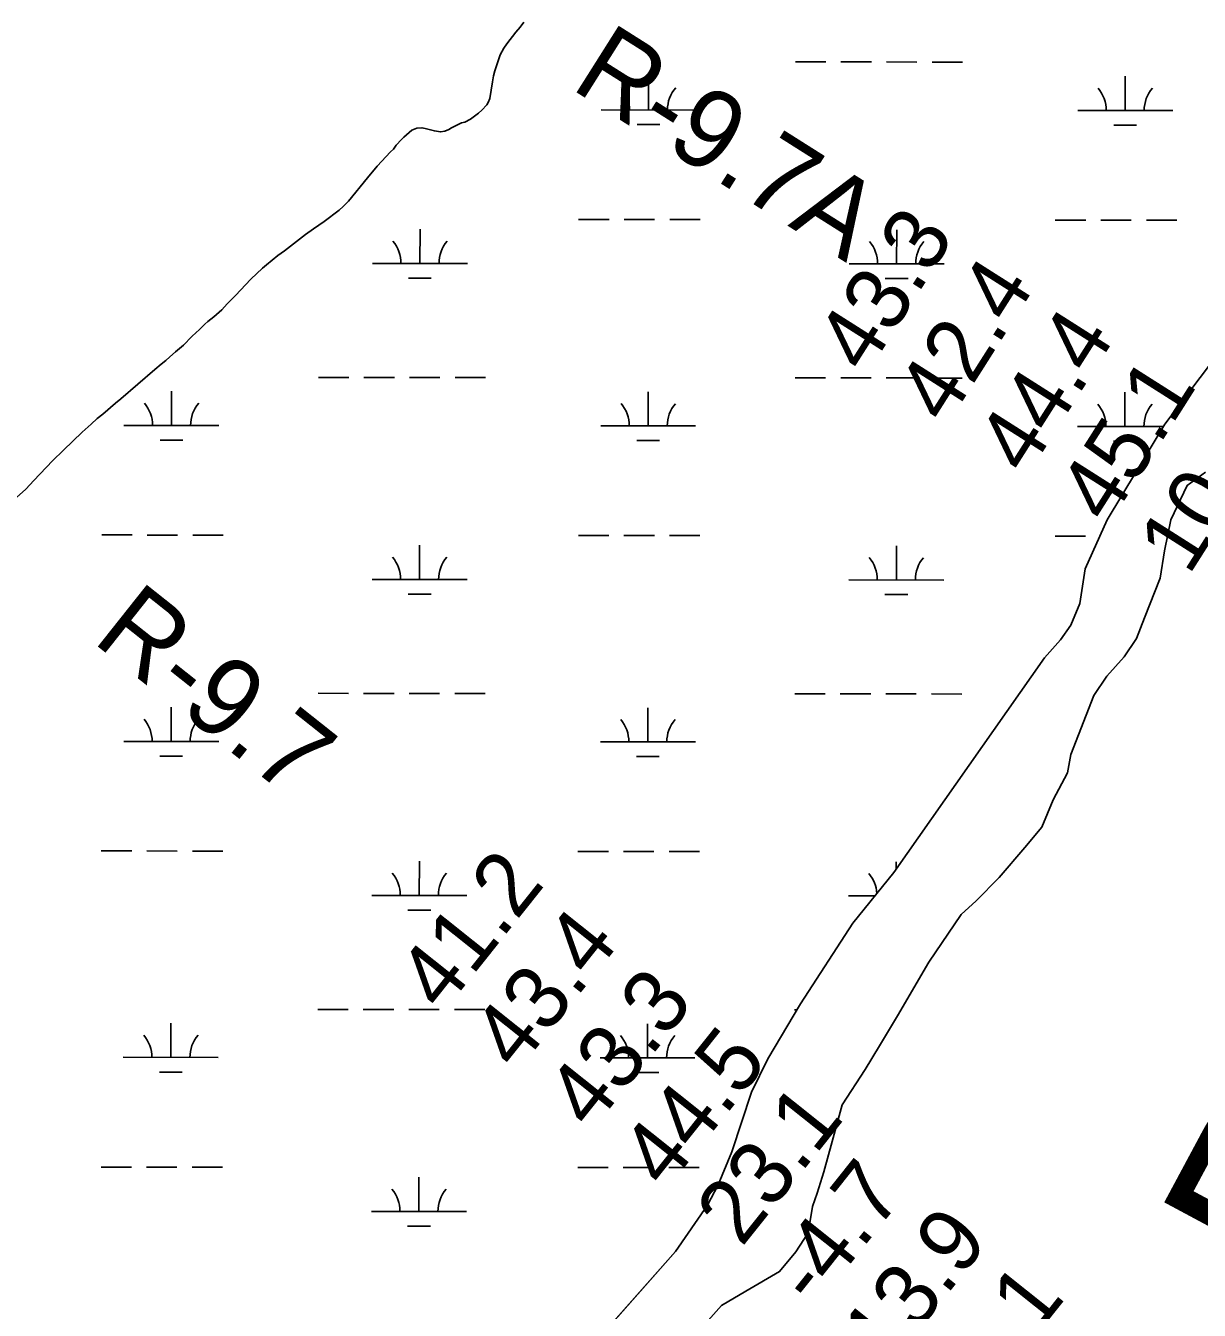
# Model space of a CAD drawing. Extents: x 3148686 to 3186545, y 916144 to 941516.
# Drawn here: x 3156578 to 3157813, y 924661 to 926013 of the extents above; entities that cross this region are included whole.
import ezdxf

# ---------------------------------------------------------------- set-up
doc = ezdxf.new("R2010")
doc.units = 0
for name, color, linetype in [('V-RIVR-EDGE', 7, 'Continuous'), ('V-RIVR-IDEN', 7, 'Continuous'), ('V-RIVR-RANG', 7, 'Continuous'), ('V-RIVR-RANG-IDEN', 7, 'Continuous'), ('V-SITE-VEGE', 7, 'Continuous'), ('V-TOPO-SHOR', 7, 'Continuous'), ('V-WETL-SWMP', 7, 'Continuous')]:
    doc.layers.add(name, color=color, linetype=linetype)

msp = doc.modelspace()

# ---------------------------------------------------------------- linework, layer by layer
at = {"layer": 'V-RIVR-EDGE'}
msp.add_lwpolyline([(3157819.9, 925543.4), (3157800.7, 925529.3), (3157783.3, 925493.1), (3157776.8, 925460.5), (3157772.1, 925431.8), (3157755.7, 925390), (3157747.1, 925368), (3157734.3, 925348.9), (3157716.2, 925328.4), (3157702.3, 925308.2), (3157678, 925245.9), (3157674.5, 925226.7), (3157659.5, 925198.4), (3157647.7, 925169.4), (3157629.6, 925148.1), (3157602.6, 925116.6), (3157578.4, 925091.9), (3157562.7, 925077.7), (3157528.6, 925027.5), (3157512.9, 925000.2), (3157496.5, 924972.6), (3157476.6, 924939.3), (3157461.6, 924914.5), (3157437.4, 924877.3), (3157426.7, 924838.7), (3157418.1, 924806.5), (3157411, 924784.1), (3157406.3, 924770), (3157401.6, 924742.3), (3157388.5, 924722.5), (3157371.4, 924701.6), (3157335.9, 924681.1), (3157310.3, 924666), (3157293.6, 924646.9)], dxfattribs=at)
at = {"layer": 'V-SITE-VEGE'}
for p, q in [((3157098.3, 926011.8), (3157093.7, 926006.6)), ((3157102.3, 926016.9), (3157098.3, 926011.8)), ((3157093.7, 926006.6), (3157084.2, 925994.2)), ((3157077.4, 925982.6), (3157071.8, 925965.8)), ((3157081, 925989.5), (3157077.4, 925982.6)), ((3157084.2, 925994.2), (3157081, 925989.5)), ((3157070.4, 925960.4), (3157069.2, 925954.3)), ((3157071.8, 925965.8), (3157070.4, 925960.4)), ((3157069.2, 925954.3), (3157066.3, 925936.5)), ((3157063.1, 925929.8), (3157058, 925924.4)), ((3157064.7, 925932.3), (3157063.1, 925929.8)), ((3157066.3, 925936.5), (3157064.7, 925932.3)), ((3157046.1, 925914.8), (3157040.1, 925911.6)), ((3157050.4, 925917.9), (3157046.1, 925914.8)), ((3157054.4, 925921.1), (3157050.4, 925917.9)), ((3157058, 925924.4), (3157054.4, 925921.1)), ((3156984.1, 925903.4), (3156975.7, 925895.9)), ((3156989.6, 925905.5), (3156984.1, 925903.4)), ((3156994.8, 925905.9), (3156989.6, 925905.5)), ((3156998.3, 925905.1), (3156994.8, 925905.9)), ((3157008, 925902.5), (3156998.3, 925905.1)), ((3157014.5, 925901.5), (3157008, 925902.5)), ((3157019.1, 925902.4), (3157014.5, 925901.5)), ((3157023.3, 925904), (3157019.1, 925902.4)), ((3157026, 925905.6), (3157023.3, 925904)), ((3157036.4, 925910.9), (3157026, 925905.6)), ((3157040.1, 925911.6), (3157036.4, 925910.9)), ((3156967.8, 925887.4), (3156964.8, 925883.4)), ((3156973.4, 925893.5), (3156967.8, 925887.4)), ((3156975.7, 925895.9), (3156973.4, 925893.5)), ((3156961.8, 925880.5), (3156947.9, 925865.3)), ((3156964.8, 925883.4), (3156961.8, 925880.5)), ((3156947.9, 925865.3), (3156937.6, 925853.1)), ((3156937.6, 925853.1), (3156917.5, 925828.6)), ((3156912.1, 925822.9), (3156907.6, 925818.9)), ((3156917.5, 925828.6), (3156912.1, 925822.9)), ((3156891.9, 925807.1), (3156880.8, 925799.3)), ((3156907.6, 925818.9), (3156891.9, 925807.1)), ((3156872.2, 925793.5), (3156850.2, 925776.4)), ((3156880.8, 925799.3), (3156872.2, 925793.5)), ((3156843.3, 925771.3), (3156831.3, 925761.6)), ((3156850.2, 925776.4), (3156843.3, 925771.3)), ((3156827.2, 925757.9), (3156814.9, 925746.3)), ((3156831.3, 925761.6), (3156827.2, 925757.9)), ((3156814.9, 925746.3), (3156798.6, 925729.1)), ((3156798.6, 925729.1), (3156789.8, 925720.4)), ((3156784.1, 925714.3), (3156775.9, 925706.8)), ((3156789.8, 925720.4), (3156784.1, 925714.3)), ((3156766.4, 925699), (3156760.4, 925693)), ((3156769.6, 925701.7), (3156766.4, 925699)), ((3156775.9, 925706.8), (3156769.6, 925701.7)), ((3156752.7, 925685.9), (3156743.7, 925677.1)), ((3156757.2, 925690.3), (3156752.7, 925685.9)), ((3156760.4, 925693), (3156757.2, 925690.3)), ((3156743.7, 925677.1), (3156735.6, 925669.8)), ((3157777, 925593.7), (3157841.7, 925679.2)), ((3156725.1, 925660.9), (3156720.5, 925656.8)), ((3156729.4, 925664.5), (3156725.1, 925660.9)), ((3156735.6, 925669.8), (3156729.4, 925664.5)), ((3156713.8, 925651.3), (3156677.8, 925620.5)), ((3156720.5, 925656.8), (3156713.8, 925651.3)), ((3156677.8, 925620.5), (3156672.1, 925616)), ((3156658.8, 925604.4), (3156653, 925599.6)), ((3156672.1, 925616), (3156658.8, 925604.4)), ((3156646.8, 925593.9), (3156637.3, 925585.5)), ((3156653, 925599.6), (3156646.8, 925593.9)), ((3157716.5, 925493.1), (3157777, 925593.7)), ((3156637.3, 925585.5), (3156617.4, 925566.5)), ((3156617.4, 925566.5), (3156606.1, 925555.3)), ((3156606.1, 925555.3), (3156586.4, 925534.4)), ((3156586.4, 925534.4), (3156577.7, 925525.3)), ((3157693.2, 925441.4), (3157716.5, 925493.1)), ((3157687.6, 925404.8), (3157693.2, 925441.4)), ((3157678.2, 925382.2), (3157687.6, 925404.8)), ((3157667.1, 925366.7), (3157678.2, 925382.2)), ((3157650.4, 925347.7), (3157667.1, 925366.7)), ((3157491.7, 925121.7), (3157650.4, 925347.7)), ((3157448.5, 925068.4), (3157491.7, 925121.7)), ((3157393.5, 924983.6), (3157448.5, 925068.4)), ((3157359.1, 924925.6), (3157393.5, 924983.6)), ((3157342, 924890.6), (3157359.1, 924925.6)), ((3157321.1, 924827.6), (3157342, 924890.6)), ((3157306.9, 924792.8), (3157321.1, 924827.6)), ((3157295.5, 924771.6), (3157306.9, 924792.8)), ((3157261.8, 924722.8), (3157295.5, 924771.6)), ((3157145.2, 924591), (3157261.8, 924722.8))]:
    msp.add_line(p, q, dxfattribs=at)
at = {"layer": 'V-TOPO-SHOR'}
for points in [[(3157014.5, 925901.5), (3157019.1, 925902.4), (3157023.3, 925904), (3157026, 925905.6), (3157036.4, 925910.9), (3157040.1, 925911.6), (3157046.1, 925914.8), (3157050.4, 925917.9), (3157054.4, 925921.1), (3157058, 925924.4), (3157063.1, 925929.8), (3157064.7, 925932.3), (3157066.3, 925936.5), (3157069.2, 925954.3), (3157070.4, 925960.4), (3157071.8, 925965.8), (3157077.4, 925982.6), (3157081, 925989.5), (3157084.2, 925994.2), (3157093.7, 926006.6), (3157098.3, 926011.8), (3157102.3, 926016.9)], [(3156565, 925513.9), (3156577.7, 925525.3), (3156586.4, 925534.4), (3156606.1, 925555.3), (3156617.4, 925566.5), (3156637.3, 925585.5), (3156646.8, 925593.9), (3156653, 925599.6), (3156658.8, 925604.4), (3156672.1, 925616), (3156677.8, 925620.5), (3156713.8, 925651.3), (3156720.5, 925656.8), (3156725.1, 925660.9), (3156729.4, 925664.5), (3156735.6, 925669.8), (3156743.7, 925677.1), (3156752.7, 925685.9), (3156757.2, 925690.3), (3156760.4, 925693), (3156766.4, 925699), (3156769.6, 925701.7), (3156775.9, 925706.8), (3156784.1, 925714.3), (3156789.8, 925720.4), (3156798.6, 925729.1), (3156814.9, 925746.3), (3156827.2, 925757.9), (3156831.3, 925761.6), (3156843.3, 925771.3), (3156850.2, 925776.4), (3156872.2, 925793.5), (3156880.8, 925799.3), (3156891.9, 925807.1), (3156907.6, 925818.9), (3156912.1, 925822.9), (3156917.5, 925828.6), (3156937.6, 925853.1), (3156947.9, 925865.3), (3156961.8, 925880.5), (3156964.8, 925883.4), (3156967.8, 925887.4), (3156973.4, 925893.5), (3156975.7, 925895.9), (3156984.1, 925903.4), (3156989.6, 925905.5), (3156994.8, 925905.9), (3156998.3, 925905.1), (3157008, 925902.5), (3157014.5, 925901.5)]]:
    msp.add_lwpolyline(points, dxfattribs=at)
at = {"layer": 'V-WETL-SWMP'}
for p, q in [((3157388.1, 925975.2), (3157420.1, 925975.1)), ((3157436.1, 925975.1), (3157468.1, 925975.1)), ((3157484.1, 925975.1), (3157516.1, 925975)), ((3157532.1, 925975), (3157564.1, 925975)), ((3157233.5, 925924.6), (3157233.5, 925960.6)), ((3157735.4, 925924.1), (3157735.4, 925960.1)), ((3157183.5, 925924.6), (3157283.5, 925924.5)), ((3157685.4, 925924.1), (3157785.4, 925924)), ((3157221.5, 925909.2), (3157245.5, 925909.2)), ((3157723.4, 925908.6), (3157747.4, 925908.6)), ((3157159.9, 925809.2), (3157191.9, 925809.2)), ((3157207.9, 925809.2), (3157239.9, 925809.2)), ((3157255.9, 925809.1), (3157287.9, 925809.1)), ((3157661.8, 925808.7), (3157693.8, 925808.7)), ((3157709.8, 925808.7), (3157741.8, 925808.6)), ((3157757.8, 925808.6), (3157789.8, 925808.6)), ((3156992.8, 925763), (3156992.9, 925799)), ((3157494.7, 925762.5), (3157494.8, 925798.5)), ((3156942.8, 925763), (3157042.8, 925762.9)), ((3157444.7, 925762.5), (3157544.7, 925762.4)), ((3156980.8, 925747.6), (3157004.8, 925747.5)), ((3157482.7, 925747), (3157506.7, 925747)), ((3156885.9, 925643), (3156917.9, 925643)), ((3156933.9, 925643), (3156965.9, 925642.9)), ((3156981.9, 925642.9), (3157013.9, 925642.9)), ((3157029.9, 925642.9), (3157061.9, 925642.8)), ((3157387.8, 925642.5), (3157419.8, 925642.5)), ((3157435.8, 925642.4), (3157467.8, 925642.4)), ((3157483.8, 925642.4), (3157515.8, 925642.4)), ((3157531.8, 925642.3), (3157563.8, 925642.3)), ((3156731.2, 925592.4), (3156731.2, 925628.4)), ((3157233.1, 925591.9), (3157233.2, 925627.9)), ((3157735, 925591.4), (3157735.1, 925627.4)), ((3156681.2, 925592.5), (3156781.2, 925592.4)), ((3157183.1, 925592), (3157283.1, 925591.9)), ((3157685, 925591.4), (3157775.6, 925591.3)), ((3156719.2, 925577), (3156743.2, 925577)), ((3157221.1, 925576.5), (3157245.1, 925576.5)), ((3157723, 925576), (3157747, 925575.9)), ((3156657.7, 925477.1), (3156689.7, 925477.1)), ((3156705.7, 925477), (3156737.7, 925477)), ((3156753.7, 925477), (3156785.7, 925477)), ((3157159.6, 925476.6), (3157191.6, 925476.5)), ((3157207.6, 925476.5), (3157239.6, 925476.5)), ((3157255.6, 925476.5), (3157287.6, 925476.4)), ((3157661.5, 925476), (3157693.5, 925476)), ((3156992.5, 925430.3), (3156992.5, 925466.3)), ((3157494.4, 925429.8), (3157494.4, 925465.8)), ((3156942.5, 925430.4), (3157042.5, 925430.3)), ((3157444.4, 925429.8), (3157544.4, 925429.7)), ((3156980.5, 925414.9), (3157004.5, 925414.9)), ((3157482.4, 925414.4), (3157506.4, 925414.3)), ((3156885.5, 925310.4), (3156917.5, 925310.3)), ((3156933.5, 925310.3), (3156965.5, 925310.3)), ((3156981.5, 925310.3), (3157013.5, 925310.2)), ((3157029.5, 925310.2), (3157061.5, 925310.2)), ((3157387.4, 925309.8), (3157419.4, 925309.8)), ((3157435.4, 925309.8), (3157467.4, 925309.7)), ((3157483.4, 925309.7), (3157515.4, 925309.7)), ((3157531.4, 925309.7), (3157563.4, 925309.6)), ((3156730.9, 925259.8), (3156730.9, 925295.8)), ((3157232.8, 925259.2), (3157232.8, 925295.2)), ((3156680.9, 925259.8), (3156780.9, 925259.7)), ((3157182.8, 925259.3), (3157282.8, 925259.2)), ((3156718.8, 925244.4), (3156742.8, 925244.3)), ((3157220.8, 925243.8), (3157244.8, 925243.8)), ((3156657.3, 925144.4), (3156689.3, 925144.4)), ((3156705.3, 925144.4), (3156737.3, 925144.3)), ((3156753.3, 925144.3), (3156785.3, 925144.3)), ((3157159.2, 925143.9), (3157191.2, 925143.9)), ((3157207.2, 925143.8), (3157239.2, 925143.8)), ((3157255.2, 925143.8), (3157287.2, 925143.8)), ((3156992.1, 925097.6), (3156992.2, 925133.6)), ((3157494.1, 925125.1), (3157494.1, 925133.1)), ((3156942.1, 925097.7), (3157042.1, 925097.6)), ((3157444, 925097.2), (3157471.8, 925097.1)), ((3156980.1, 925082.2), (3157004.1, 925082.2)), ((3156885.2, 924977.7), (3156917.2, 924977.6)), ((3156933.2, 924977.6), (3156965.2, 924977.6)), ((3156981.2, 924977.6), (3157013.2, 924977.5)), ((3157029.2, 924977.5), (3157061.2, 924977.5)), ((3157387.1, 924977.1), (3157389.7, 924977.1)), ((3156730.5, 924927.1), (3156730.5, 924963.1)), ((3157232.4, 924926.6), (3157232.5, 924962.6)), ((3156680.5, 924927.2), (3156780.5, 924927)), ((3157182.4, 924926.6), (3157282.4, 924926.5)), ((3156718.5, 924911.7), (3156742.5, 924911.7)), ((3157220.4, 924911.2), (3157244.4, 924911.1)), ((3156657, 924811.7), (3156689, 924811.7)), ((3156705, 924811.7), (3156737, 924811.7)), ((3156753, 924811.6), (3156785, 924811.6)), ((3157158.9, 924811.2), (3157190.9, 924811.2)), ((3157206.9, 924811.2), (3157238.9, 924811.1)), ((3157254.9, 924811.1), (3157286.9, 924811.1)), ((3156991.8, 924765), (3156991.8, 924801)), ((3156941.8, 924765), (3157041.8, 924764.9)), ((3156979.8, 924749.5), (3157003.8, 924749.5))]:
    msp.add_line(p, q, dxfattribs=at)
for points in [[(3157102.3, 926016.9), (3157098.3, 926011.8), (3157093.7, 926006.6), (3157084.2, 925994.2), (3157081, 925989.5), (3157077.4, 925982.6), (3157071.8, 925965.8), (3157070.4, 925960.4), (3157069.2, 925954.3), (3157066.3, 925936.5), (3157064.7, 925932.3), (3157063.1, 925929.8), (3157058, 925924.4), (3157054.4, 925921.1), (3157050.4, 925917.9), (3157046.1, 925914.8), (3157040.1, 925911.6), (3157036.4, 925910.9), (3157026, 925905.6), (3157023.3, 925904), (3157019.1, 925902.4), (3157014.5, 925901.5), (3157008, 925902.5), (3156998.3, 925905.1), (3156994.8, 925905.9), (3156989.6, 925905.5), (3156984.1, 925903.4), (3156975.7, 925895.9), (3156973.4, 925893.5), (3156967.8, 925887.4), (3156964.8, 925883.4), (3156961.8, 925880.5), (3156947.9, 925865.3), (3156937.6, 925853.1), (3156917.5, 925828.6), (3156912.1, 925822.9), (3156907.6, 925818.9), (3156891.9, 925807.1), (3156880.8, 925799.3), (3156872.2, 925793.5), (3156850.2, 925776.4), (3156843.3, 925771.3), (3156831.3, 925761.6), (3156827.2, 925757.9), (3156814.9, 925746.3), (3156798.6, 925729.1), (3156789.8, 925720.4), (3156784.1, 925714.3), (3156775.9, 925706.8), (3156769.6, 925701.7), (3156766.4, 925699), (3156760.4, 925693), (3156757.2, 925690.3), (3156752.7, 925685.9), (3156743.7, 925677.1), (3156735.6, 925669.8), (3156729.4, 925664.5), (3156725.1, 925660.9), (3156720.5, 925656.8), (3156713.8, 925651.3), (3156677.8, 925620.5), (3156672.1, 925616), (3156658.8, 925604.4), (3156653, 925599.6), (3156646.8, 925593.9), (3156637.3, 925585.5), (3156617.4, 925566.5), (3156606.1, 925555.3), (3156586.4, 925534.4), (3156577.7, 925525.3), (3156565, 925513.9)], [(3157145.2, 924591), (3157261.8, 924722.8), (3157295.5, 924771.6), (3157306.9, 924792.8), (3157321.1, 924827.6), (3157342, 924890.6), (3157359.1, 924925.6), (3157393.5, 924983.6), (3157448.5, 925068.4), (3157491.7, 925121.7), (3157650.4, 925347.7), (3157667.1, 925366.7), (3157678.2, 925382.2), (3157687.6, 925404.8), (3157693.2, 925441.4), (3157716.5, 925493.1), (3157777, 925593.7), (3157841.7, 925679.2)]]:
    msp.add_lwpolyline(points, dxfattribs=at)
for centre, start, end in [((3157178.2, 925925.1), 359.1678, 40.7115), ((3157288.7, 925925), 139.1678, 180.7115), ((3157680.1, 925924.6), 359.1678, 40.7115), ((3157790.6, 925924.5), 139.1678, 180.7115), ((3156937.6, 925763.5), 359.1678, 40.7115), ((3157048.1, 925763.4), 139.1678, 180.7115), ((3157439.5, 925763), 359.1678, 40.7115), ((3157550, 925762.9), 139.1678, 180.7115), ((3156676, 925593), 359.1678, 40.7115), ((3156786.5, 925592.9), 139.1678, 180.7115), ((3157177.9, 925592.5), 359.1678, 40.7115), ((3157288.4, 925592.3), 139.1678, 180.7115), ((3157679.8, 925591.9), 359.1678, 40.7115), ((3157790.3, 925591.8), 139.1678, 180.7115), ((3156937.2, 925430.8), 359.1678, 40.7115), ((3157047.7, 925430.7), 139.1678, 180.7115), ((3157439.1, 925430.3), 359.1678, 40.7115), ((3157549.6, 925430.2), 139.1678, 180.7115), ((3156675.6, 925260.3), 359.1678, 40.7115), ((3156786.1, 925260.2), 139.1678, 180.7115), ((3157177.5, 925259.8), 359.1678, 40.7115), ((3157288, 925259.7), 139.1678, 180.7115), ((3156936.9, 925098.2), 359.1678, 40.7115), ((3157047.4, 925098.1), 139.1678, 180.7115), ((3157438.8, 925097.6), 3.6015, 40.7115), ((3156675.3, 924927.6), 359.1678, 40.7115), ((3156785.8, 924927.5), 139.1678, 180.7115), ((3157177.2, 924927.1), 359.1678, 40.7115), ((3157287.7, 924927), 139.1678, 180.7115), ((3156936.5, 924765.5), 359.1678, 40.7115), ((3157047, 924765.4), 139.1678, 180.7115)]:
    msp.add_arc(centre, 35.2, start, end, dxfattribs=at)

# ---------------------------------------------------------------- texts
at = {"layer": 'V-RIVR-IDEN'}
msp.add_text('R    E    D', height=200, rotation=61.7774, dxfattribs=at).set_placement((3157942.3, 924660.6))
at = {"layer": 'V-RIVR-RANG'}
for s, rotation, p in [('43.3', 57.5683, (3157462.8, 925645)), ('42.4', 57.5683, (3157547.4, 925591.6)), ('44.4', 57.5683, (3157631.9, 925538.2)), ('45.1', 57.5683, (3157717.7, 925486.8)), ('10.1', 57.5683, (3157802.2, 925433.4)), ('41.2', 51.4283, (3157016.7, 924973.2)), ('43.4', 51.4283, (3157095, 924911.1)), ('43.3', 51.4283, (3157173.4, 924848.9)), ('44.5', 51.4283, (3157251.7, 924786.7)), ('23.1', 51.4283, (3157331.5, 924726.4)), ('-4.7', 51.4283, (3157408.4, 924662.4)), ('-13.9', 51.4283, (3157465.8, 924574.1)), ('-18.1', 51.4283, (3157545.8, 924514))]:
    msp.add_text(s, height=67, rotation=rotation, dxfattribs=at).set_placement(p)
at = {"layer": 'V-RIVR-RANG-IDEN'}
for s, rotation, p in [('R-9.7A', 327.7137, (3157150, 925947.9)), ('R-9.7', 321.5658, (3156646.5, 925365.3))]:
    msp.add_text(s, height=83, rotation=rotation, dxfattribs=at).set_placement(p)

doc.saveas('drawing.dxf')
